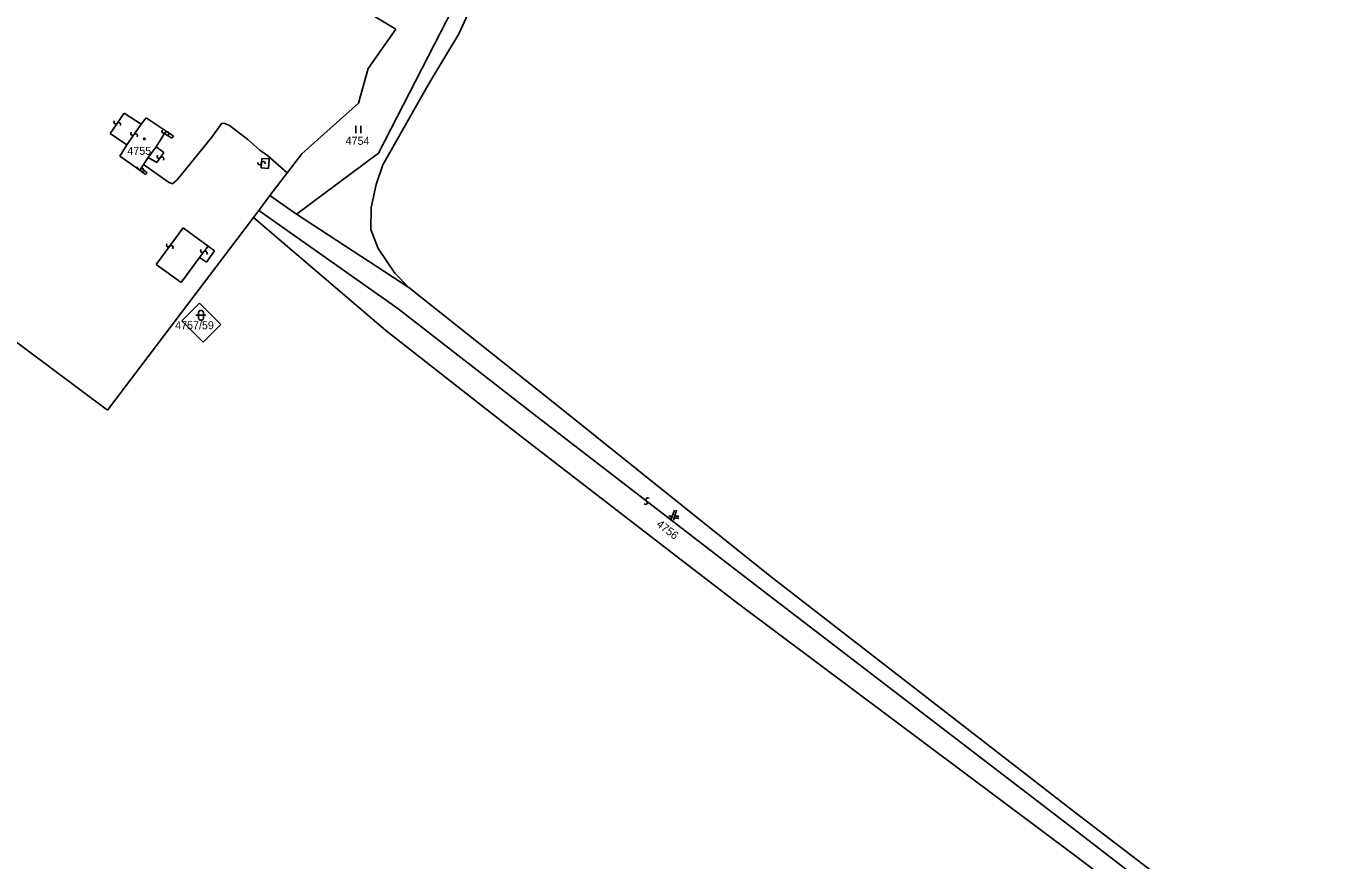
# Model space of a CAD drawing. Extents: x -266179 to -264727, y -1243225 to -1241702.
# Drawn here: x -265832.8 to -265573.7, y -1242667.5 to -1242500.7 of the extents above; entities that cross this region are included whole.
import ezdxf

# ---------------------------------------------------------------- set-up
doc = ezdxf.new("R2010")
doc.units = 0
for name, color, linetype in [('Vrstva 1', 7, 'Continuous'), ('Vrstva 2', 7, 'Continuous'), ('Vrstva 63', 7, 'Continuous')]:
    doc.layers.add(name, color=color, linetype=linetype)

msp = doc.modelspace()

# ---------------------------------------------------------------- linework, layer by layer
at = {"layer": 'Vrstva 1'}
for p, q in [((-265758.84, -1242501.35), (-265828.81, -1242459.15)), ((-265741.58, -1242492.03), (-265746.31, -1242502.4)), ((-265762.31, -1242526.16), (-265745.08, -1242492.57)), ((-265764.4, -1242509.21), (-265758.84, -1242501.35)), ((-265746.31, -1242502.4), (-265752.16, -1242512.18)), ((-265766.28, -1242516.12), (-265764.4, -1242509.21)), ((-265752.16, -1242512.18), (-265761.42, -1242528.47)), ((-265777.64, -1242526.28), (-265766.28, -1242516.12)), ((-265766.85, -1242520.67), (-265766.85, -1242522.17)), ((-265765.85, -1242522.17), (-265765.85, -1242520.67)), ((-265816.51, -1242577.54), (-265883.27, -1242527.58)), ((-265784.05, -1242534.59), (-265777.64, -1242526.28)), ((-265778.7, -1242538.34), (-265762.31, -1242526.16)), ((-265761.42, -1242528.47), (-265762.77, -1242532.4)), ((-265762.77, -1242532.4), (-265763.78, -1242536.97)), ((-265784.05, -1242534.59), (-265786.22, -1242537.62)), ((-265778.7, -1242538.34), (-265784.05, -1242534.59)), ((-265786.22, -1242537.62), (-265787.3, -1242539.01)), ((-265756.27, -1242552.99), (-265778.7, -1242538.34)), ((-265763.78, -1242536.97), (-265763.81, -1242541.4)), ((-265787.3, -1242539.01), (-265816.51, -1242577.54)), ((-265760.83, -1242561.56), (-265787.3, -1242539.01)), ((-265763.81, -1242541.4), (-265762.4, -1242545.2)), ((-265762.4, -1242545.2), (-265759.05, -1242550.12)), ((-265759.05, -1242550.12), (-265756.27, -1242552.99)), ((-265756.27, -1242552.99), (-265728.07, -1242575.37)), ((-265801.62, -1242559.64), (-265798.08, -1242556.11)), ((-265798.08, -1242556.11), (-265793.84, -1242560.36)), ((-265797.38, -1242563.89), (-265801.62, -1242559.64)), ((-265793.84, -1242560.36), (-265797.38, -1242563.89)), ((-265734.37, -1242582.34), (-265760.83, -1242561.56)), ((-265728.07, -1242575.37), (-265684.07, -1242610.63)), ((-265702.92, -1242606.56), (-265734.37, -1242582.34)), ((-265703.16, -1242597.49), (-265703.86, -1242599.49)), ((-265703.36, -1242599.49), (-265702.76, -1242597.49)), ((-265703.58, -1242598.69), (-265704.26, -1242598.69)), ((-265704.26, -1242599.09), (-265703.72, -1242599.09)), ((-265703.24, -1242599.09), (-265702.26, -1242599.09)), ((-265702.26, -1242598.69), (-265703.12, -1242598.69)), ((-265690.28, -1242616.29), (-265702.92, -1242606.56)), ((-265684.07, -1242610.63), (-265622.77, -1242658.15)), ((-265622.93, -1242666.67), (-265690.28, -1242616.29)), ((-265622.77, -1242658.15), (-265574.91, -1242694.62)), ((-265607.5, -1242678.29), (-265622.93, -1242666.67))]:
    msp.add_line(p, q, dxfattribs=at)
for points in [[(-265809.01, -1242523.12), (-265808.92, -1242523.27), (-265809.01, -1242523.42), (-265809.19, -1242523.42), (-265809.28, -1242523.27), (-265809.19, -1242523.12)], [(-265798.3, -1242558.03), (-265798.2, -1242557.74), (-265797.95, -1242557.56), (-265797.64, -1242557.56), (-265797.39, -1242557.74), (-265797.29, -1242558.03), (-265797.29, -1242559.03), (-265797.39, -1242559.32), (-265797.64, -1242559.5), (-265797.95, -1242559.5), (-265798.2, -1242559.32), (-265798.3, -1242559.03)]]:
    msp.add_lwpolyline(points, close=True, dxfattribs=at)
msp.add_lwpolyline([(-265798.8, -1242558.53), (-265797.53, -1242558.53), (-265796.8, -1242558.53)], dxfattribs=at)
at = {"layer": 'Vrstva 2'}
for p, q in [((-265813.12, -1242518.13), (-265815.93, -1242522.2)), ((-265809.74, -1242520.36), (-265813.12, -1242518.13)), ((-265812.59, -1242524.47), (-265809.74, -1242520.36)), ((-265809.74, -1242520.36), (-265808.73, -1242519.07)), ((-265808.73, -1242519.07), (-265804.77, -1242521.77)), ((-265815.93, -1242522.2), (-265812.59, -1242524.47)), ((-265805.07, -1242522.24), (-265806.78, -1242524.86)), ((-265805.07, -1242522.24), (-265804.77, -1242521.77)), ((-265803.62, -1242523.13), (-265805.07, -1242522.24)), ((-265804.77, -1242521.77), (-265803.32, -1242522.75)), ((-265803.32, -1242522.75), (-265803.62, -1242523.13)), ((-265814.03, -1242526.76), (-265812.59, -1242524.47)), ((-265808.34, -1242527), (-265806.78, -1242524.86)), ((-265806.78, -1242524.86), (-265805.2, -1242526.04)), ((-265810.03, -1242529.53), (-265814.03, -1242526.76)), ((-265808.34, -1242527), (-265809.75, -1242529.13)), ((-265806.6, -1242528.04), (-265808.34, -1242527)), ((-265805.2, -1242526.04), (-265806.6, -1242528.04)), ((-265785.77, -1242529.09), (-265785.61, -1242527.18)), ((-265785.61, -1242527.18), (-265784.14, -1242527.3)), ((-265784.14, -1242527.3), (-265784.31, -1242529.22)), ((-265810.03, -1242529.53), (-265809.75, -1242529.13)), ((-265808.91, -1242530.42), (-265810.03, -1242529.53)), ((-265809.75, -1242529.13), (-265808.56, -1242530.07)), ((-265808.56, -1242530.07), (-265808.91, -1242530.42)), ((-265784.31, -1242529.22), (-265785.77, -1242529.09)), ((-265786.22, -1242537.62), (-265758.41, -1242557.19)), ((-265806.75, -1242548.39), (-265801.35, -1242541.1)), ((-265801.35, -1242541.1), (-265796.38, -1242544.75)), ((-265796.38, -1242544.75), (-265798.06, -1242547.01)), ((-265795.07, -1242545.64), (-265796.66, -1242547.91)), ((-265796.38, -1242544.75), (-265795.07, -1242545.64)), ((-265801.76, -1242552), (-265806.75, -1242548.39)), ((-265798.06, -1242547.01), (-265801.76, -1242552)), ((-265796.66, -1242547.91), (-265798.06, -1242547.01)), ((-265758.41, -1242557.19), (-265731.19, -1242578.35)), ((-265731.19, -1242578.35), (-265686.22, -1242613.04)), ((-265686.22, -1242613.04), (-265623.46, -1242661.11)), ((-265623.46, -1242661.11), (-265573.67, -1242699.47))]:
    msp.add_line(p, q, dxfattribs=at)
for points in [[(-265813.936, -1242520.632), (-265813.851, -1242520.315), (-265814.035, -1242520.054), (-265814.32, -1242520.027), (-265814.769, -1242520.325), (-265815.073, -1242520.236), (-265815.204, -1242519.951), (-265815.114, -1242519.698)], [(-265811.753, -1242521.946), (-265811.839, -1242522.264), (-265811.655, -1242522.525), (-265811.37, -1242522.553), (-265810.921, -1242522.256), (-265810.617, -1242522.345), (-265810.487, -1242522.63), (-265810.577, -1242522.884)], [(-265805.525, -1242521.56), (-265805.599, -1242521.88), (-265805.406, -1242522.134), (-265805.12, -1242522.151), (-265804.682, -1242521.837), (-265804.375, -1242521.914), (-265804.234, -1242522.194), (-265804.315, -1242522.45)], [(-265805.314, -1242527.511), (-265805.227, -1242527.194), (-265805.409, -1242526.932), (-265805.694, -1242526.903), (-265806.145, -1242527.198), (-265806.448, -1242527.108), (-265806.578, -1242526.822), (-265806.486, -1242526.569)], [(-265786.433, -1242528.022), (-265786.35, -1242528.341), (-265786.06, -1242528.475), (-265785.799, -1242528.357), (-265785.558, -1242527.875), (-265785.25, -1242527.801), (-265784.995, -1242527.983), (-265784.947, -1242528.248)], [(-265810.476, -1242528.859), (-265810.563, -1242529.176), (-265810.381, -1242529.438), (-265810.096, -1242529.467), (-265809.645, -1242529.172), (-265809.342, -1242529.262), (-265809.213, -1242529.548), (-265809.304, -1242529.801)], [(-265804.623, -1242544.258), (-265804.719, -1242544.573), (-265804.543, -1242544.84), (-265804.259, -1242544.876), (-265803.801, -1242544.594), (-265803.5, -1242544.692), (-265803.379, -1242544.981), (-265803.477, -1242545.232)], [(-265796.648, -1242546.368), (-265796.551, -1242546.053), (-265796.726, -1242545.786), (-265797.011, -1242545.749), (-265797.469, -1242546.031), (-265797.77, -1242545.932), (-265797.891, -1242545.643), (-265797.792, -1242545.392)], [(-265708.207, -1242595.132), (-265708.52, -1242595.029), (-265708.79, -1242595.2), (-265708.832, -1242595.483), (-265708.558, -1242595.947), (-265708.663, -1242596.246), (-265708.954, -1242596.362), (-265709.203, -1242596.258)]]:
    msp.add_lwpolyline(points, dxfattribs=at)
at = {"layer": 'Vrstva 63'}
for p, q in [((-265795.64, -1242522.95), (-265793.61, -1242520.17)), ((-265793.61, -1242520.17), (-265793.01, -1242520.23)), ((-265793.01, -1242520.23), (-265792.12, -1242520.6)), ((-265792.12, -1242520.6), (-265788.45, -1242523.44)), ((-265802.53, -1242531.45), (-265795.64, -1242522.95)), ((-265788.45, -1242523.44), (-265786, -1242525.57)), ((-265786, -1242525.57), (-265784.53, -1242526.59)), ((-265809.26, -1242528.38), (-265804.27, -1242531.92)), ((-265784.53, -1242526.59), (-265780.56, -1242530.07)), ((-265804.27, -1242531.92), (-265803.51, -1242532.29)), ((-265803.51, -1242532.29), (-265802.53, -1242531.45))]:
    msp.add_line(p, q, dxfattribs=at)

# ---------------------------------------------------------------- texts
at = {"layer": 'Vrstva 1'}
for s, p in [('4754', (-265768.878, -1242524.47)), ('4755', (-265812.508, -1242526.48)), ('4757/59', (-265802.958, -1242561.34))]:
    msp.add_text(s, height=1.6, dxfattribs=at).set_placement(p)
msp.add_text('4756', height=1.6, rotation=322.23146, dxfattribs=at).set_placement((-265706.876, -1242600.581))

doc.saveas('drawing.dxf')
